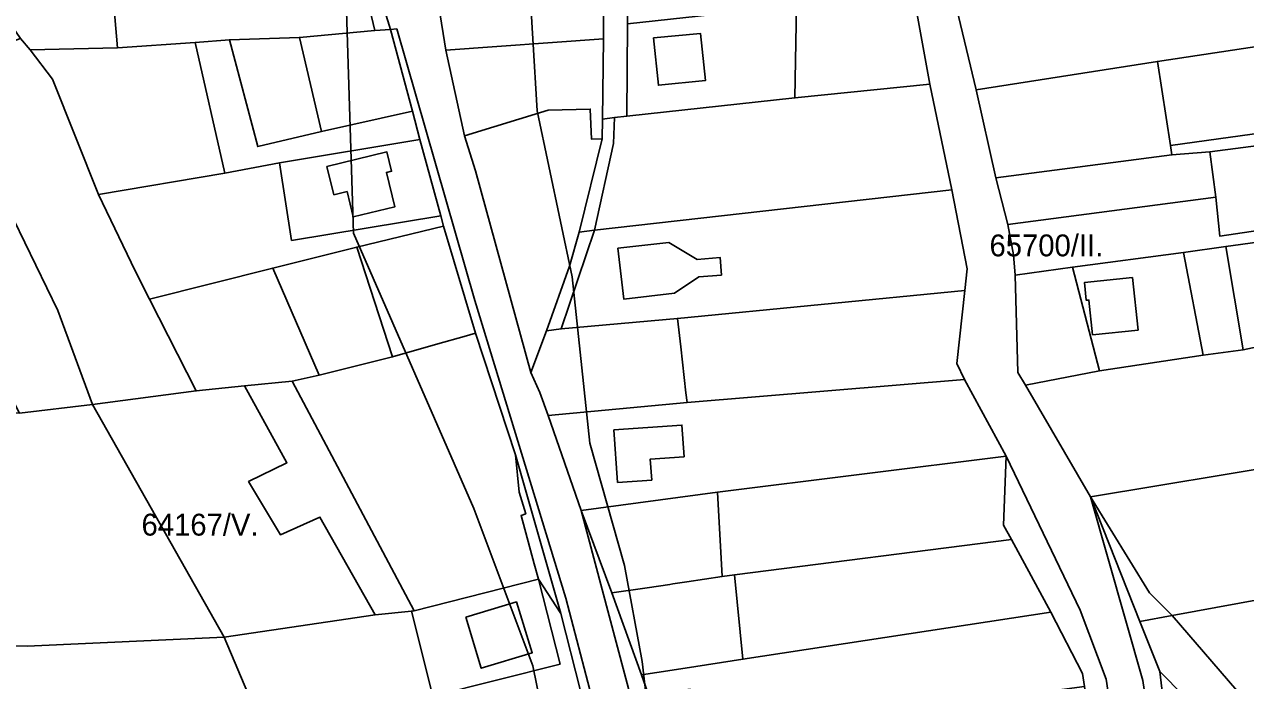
# Model space of a CAD drawing. Extents: x -521261 to -517465, y -1182764 to -1179456.
# Drawn here: x -519763.3 to -519484, y -1180677.3 to -1180527.3 of the extents above; entities that cross this region are included whole.
import ezdxf

# ---------------------------------------------------------------- set-up
doc = ezdxf.new("R2010")
doc.units = 0
for name, color, linetype in [('95560013', 7, 'Continuous'), ('95590013', 7, 'Continuous'), ('95600013', 7, 'Continuous'), ('95610013', 7, 'Continuous'), ('95630013', 7, 'Continuous'), ('95640013', 7, 'Continuous'), ('95660013', 7, 'Continuous')]:
    doc.layers.add(name, color=color, linetype=linetype)

msp = doc.modelspace()

# ---------------------------------------------------------------- linework, layer by layer
at = {"layer": '95560013'}
for points in [[(-519625.22, -1180519.95), (-519563.84, -1180512.91), (-519559.42, -1180523.34), (-519556.23, -1180540.88), (-519587.06, -1180544.07), (-519586.67, -1180522.95), (-519625.35, -1180527.12)], [(-519587.06, -1180544.07), (-519556.23, -1180540.88), (-519551.14, -1180565.07), (-519632.93, -1180574.33), (-519628.57, -1180554.5), (-519628.3, -1180548.57), (-519625.48, -1180548.2)]]:
    msp.add_lwpolyline(points, close=True, dxfattribs=at)
at = {"layer": '95590013'}
for points in [[(-519481.29, -1180509.48), (-519457.44, -1180505.68), (-519449, -1180527.32), (-519457.6, -1180528.65), (-519463.53, -1180529.56), (-519476.08, -1180531.51), (-519480.43, -1180532.18), (-519504.16, -1180535.7), (-519545.59, -1180542.18), (-519550.45, -1180521.83)], [(-519586.67, -1180522.95), (-519587.06, -1180544.07), (-519625.48, -1180548.2), (-519625.35, -1180527.12)], [(-519457.6, -1180528.65), (-519449, -1180527.32), (-519443.22, -1180543.16), (-519444.59, -1180547.12), (-519501.17, -1180554.98), (-519504.16, -1180535.7), (-519480.43, -1180532.18), (-519479.66, -1180537.12), (-519478.23, -1180546.41), (-519461.33, -1180543.8), (-519455.4, -1180542.88)], [(-519716.41, -1180530.74), (-519709.92, -1180555.2), (-519695.32, -1180551.74), (-519674.54, -1180547.09), (-519672.84, -1180553.61), (-519704.93, -1180558.88), (-519717.41, -1180561.26), (-519724.26, -1180531.4)], [(-519700.39, -1180530.21), (-519695.32, -1180551.74), (-519709.92, -1180555.2), (-519716.41, -1180530.74)], [(-519666.88, -1180533.11), (-519630.81, -1180530.53), (-519631.09, -1180548.95), (-519631.17, -1180553.45), (-519633.59, -1180553.49), (-519633.88, -1180546.6), (-519643.47, -1180546.88), (-519662.64, -1180552.73)], [(-519619.39, -1180530.32), (-519618.27, -1180541.18), (-519607.52, -1180540.08), (-519608.63, -1180529.33)], [(-519545.59, -1180542.18), (-519504.16, -1180535.7), (-519501.17, -1180554.98), (-519500.84, -1180557.1), (-519541.11, -1180562.36)], [(-519444.59, -1180547.12), (-519445.79, -1180550.4), (-519492.15, -1180556.42), (-519500.84, -1180557.1), (-519501.17, -1180554.98)], [(-519445.79, -1180550.4), (-519447.22, -1180555.01), (-519448.8, -1180555.21), (-519450.48, -1180568.08), (-519450.58, -1180569.86), (-519454.03, -1180570.32), (-519489.86, -1180575.7), (-519490.8, -1180566.75), (-519492.15, -1180556.42)], [(-519500.84, -1180557.1), (-519492.15, -1180556.42), (-519490.8, -1180566.75), (-519538.35, -1180572.99), (-519541.11, -1180562.36)], [(-519632.93, -1180574.33), (-519551.14, -1180565.07), (-519547.64, -1180583.16), (-519548.23, -1180588.14), (-519613.95, -1180594.5), (-519640.49, -1180596.89)], [(-519538.35, -1180572.99), (-519490.8, -1180566.75), (-519489.86, -1180575.7), (-519454.03, -1180570.32), (-519453.95, -1180573.29), (-519488.53, -1180578.08), (-519498.22, -1180579.41), (-519523.6, -1180582.79), (-519536.72, -1180584.57), (-519537.04, -1180579.93)], [(-519488.53, -1180578.08), (-519453.95, -1180573.29), (-519455.66, -1180597.28), (-519476.71, -1180600.04), (-519484.55, -1180601.67)], [(-519615.93, -1180577.1), (-519627.55, -1180578.46), (-519626.19, -1180590.08), (-519614.57, -1180588.72), (-519609.05, -1180585.01), (-519603.87, -1180584.59), (-519604.17, -1180580.55), (-519609.43, -1180580.99)], [(-519498.22, -1180579.41), (-519488.53, -1180578.08), (-519484.55, -1180601.67), (-519493.71, -1180602.87)], [(-519734.67, -1180590.12), (-519706.47, -1180582.97), (-519695.88, -1180607.5), (-519702.07, -1180608.86), (-519712.92, -1180609.9), (-519723.97, -1180611.09)], [(-519536.72, -1180584.57), (-519523.6, -1180582.79), (-519517.41, -1180606.51), (-519534.35, -1180609.75), (-519536.05, -1180606.88)], [(-519548.23, -1180588.14), (-519550.02, -1180604.84), (-519548.25, -1180608.47), (-519611.74, -1180613.76), (-519612.01, -1180611.52), (-519613.15, -1180600.98), (-519613.95, -1180594.5)], [(-519484.55, -1180601.67), (-519476.71, -1180600.04), (-519473.5, -1180627.72), (-519519.49, -1180635.3), (-519534.35, -1180609.75), (-519517.41, -1180606.51), (-519493.71, -1180602.87)], [(-519548.25, -1180608.47), (-519538.72, -1180626.02), (-519604.76, -1180634.22), (-519635.98, -1180638.42), (-519643.53, -1180616.69), (-519611.74, -1180613.76)], [(-519628.48, -1180619.97), (-519627.63, -1180632), (-519619.82, -1180631.47), (-519620.14, -1180626.68), (-519612.41, -1180626.15), (-519612.9, -1180618.91)], [(-519538.72, -1180626.02), (-519539.34, -1180641.78), (-519537.56, -1180645.04), (-519600.87, -1180653.15), (-519603.71, -1180653.57), (-519604.76, -1180634.22)], [(-519473.5, -1180627.72), (-519471.99, -1180627.46), (-519464.58, -1180655.8), (-519500.79, -1180662.46), (-519505.99, -1180657.26), (-519519.49, -1180635.3)], [(-519537.56, -1180645.04), (-519528.51, -1180661.68), (-519598.97, -1180672.46), (-519600.87, -1180653.15)], [(-519674.13, -1180661.38), (-519645.67, -1180654.18), (-519640.77, -1180673.57), (-519669.85, -1180680.93), (-519674.76, -1180661.45)], [(-519500.79, -1180662.46), (-519464.58, -1180655.8), (-519456.63, -1180686.88), (-519478.81, -1180687.89)], [(-519662.3, -1180662.86), (-519658.8, -1180674.51), (-519647.15, -1180670.98), (-519650.76, -1180659.34)], [(-519528.51, -1180661.68), (-519521.28, -1180675.74), (-519520.86, -1180678.68), (-519560.03, -1180683.88), (-519599.96, -1180689.65), (-519609.08, -1180691.16), (-519610.98, -1180679.31), (-519617.01, -1180680.21), (-519615.19, -1180692.17), (-519615.35, -1180692.21), (-519619.51, -1180692.9), (-519620.34, -1180681.18), (-519622.17, -1180676.01), (-519618.65, -1180675.5), (-519612.16, -1180674.5), (-519598.97, -1180672.46)], [(-519492.54, -1180686.48), (-519490.6, -1180689.84), (-519501.68, -1180691.54), (-519503.59, -1180675.27)]]:
    msp.add_lwpolyline(points, close=True, dxfattribs=at)
at = {"layer": '95600013'}
msp.add_lwpolyline([(-519708.21, -1180689.61), (-519717.59, -1180667.43), (-519683.07, -1180662.31), (-519674.76, -1180661.45), (-519669.85, -1180680.93), (-519640.77, -1180673.57), (-519645.67, -1180654.18), (-519640.61, -1180662.03), (-519636.11, -1180679.72)], dxfattribs=at)
at = {"layer": '95610013'}
for points in [[(-519701.4, -1180452.03), (-519683.11, -1180528.64), (-519700.39, -1180530.21), (-519716.41, -1180530.74), (-519724.26, -1180531.4), (-519741.98, -1180532.57), (-519742.58, -1180525.52), (-519747.26, -1180461.14), (-519737.48, -1180458.88), (-519711.33, -1180453.82)], [(-519755.56, -1180462.83), (-519747.26, -1180461.14), (-519742.58, -1180525.52), (-519741.98, -1180532.57), (-519762, -1180533.09), (-519764.17, -1180530.48), (-519769.07, -1180523.42), (-519771.26, -1180514.7)], [(-519670.07, -1180513.08), (-519630.86, -1180510.85), (-519630.85, -1180520.26), (-519630.81, -1180530.53), (-519666.88, -1180533.11)], [(-519762, -1180533.09), (-519756.87, -1180539.77), (-519746.34, -1180566.13), (-519737.99, -1180583.64), (-519734.67, -1180590.12), (-519723.97, -1180611.09), (-519747.7, -1180614.18), (-519755.66, -1180592.71), (-519768.22, -1180566.74), (-519787.11, -1180538.74), (-519764.17, -1180530.48)], [(-519724.26, -1180531.4), (-519717.41, -1180561.26), (-519746.34, -1180566.13), (-519756.87, -1180539.77), (-519762, -1180533.09), (-519741.98, -1180532.57)], [(-519787.11, -1180538.74), (-519768.22, -1180566.74), (-519755.66, -1180592.71), (-519747.7, -1180614.18), (-519764.44, -1180616.17), (-519787.86, -1180570.19), (-519797.31, -1180557.63), (-519806.32, -1180548.59), (-519809.29, -1180545.42), (-519790.04, -1180534.46)], [(-519717.41, -1180561.26), (-519704.93, -1180558.88), (-519702.19, -1180576.67), (-519668.07, -1180571.07), (-519667.42, -1180573.37), (-519687.29, -1180578.17), (-519706.47, -1180582.97), (-519734.67, -1180590.12), (-519737.99, -1180583.64), (-519746.34, -1180566.13)], [(-519723.97, -1180611.09), (-519712.92, -1180609.9), (-519703.26, -1180627.51), (-519712, -1180631.84), (-519704.72, -1180643.99), (-519695.69, -1180639.95), (-519683.07, -1180662.31), (-519717.59, -1180667.43), (-519747.7, -1180614.18)], [(-519764.44, -1180616.17), (-519747.7, -1180614.18), (-519717.59, -1180667.43), (-519762.68, -1180669.48), (-519814.85, -1180668.94), (-519850.9, -1180639.04), (-519846.5, -1180637.75), (-519801.28, -1180626.06), (-519801.81, -1180615.54)], [(-519717.59, -1180667.43), (-519708.21, -1180689.61), (-519692.2, -1180746.98), (-519697.59, -1180747.55), (-519712.21, -1180749.16), (-519717.76, -1180748.91), (-519756.77, -1180721.21), (-519783.25, -1180694.48), (-519803.71, -1180675.31), (-519814.85, -1180668.94), (-519762.68, -1180669.48)]]:
    msp.add_lwpolyline(points, close=True, dxfattribs=at)
at = {"layer": '95630013'}
for points in [[(-519550.45, -1180521.83), (-519545.59, -1180542.18), (-519541.11, -1180562.36), (-519538.35, -1180572.99), (-519537.04, -1180579.93), (-519536.72, -1180584.57), (-519536.05, -1180606.88), (-519534.35, -1180609.75), (-519519.49, -1180635.3), (-519507.5, -1180677.34), (-519496.47, -1180751.4), (-519475.99, -1180798.26), (-519473.15, -1180811.61), (-519470.44, -1180842.25), (-519488.4, -1180904.99), (-519493.48, -1180935.68), (-519491.42, -1180951.86), (-519435.57, -1181123.54)], [(-519435.91, -1181162.44), (-519445.77, -1181119.72), (-519502.58, -1180941.01), (-519495.82, -1180898.23), (-519478.12, -1180840), (-519478.91, -1180815.91), (-519482.79, -1180802.48), (-519493.4, -1180779.68), (-519502.51, -1180755.33), (-519501.84, -1180755.2), (-519503.49, -1180741.14), (-519501.57, -1180737.28), (-519506.63, -1180738.29), (-519515.84, -1180677.04), (-519521.8, -1180661.26), (-519538.72, -1180626.02), (-519548.25, -1180608.47), (-519550.02, -1180604.84), (-519548.23, -1180588.14), (-519547.64, -1180583.16), (-519551.14, -1180565.07), (-519556.23, -1180540.88), (-519559.42, -1180523.34)]]:
    msp.add_lwpolyline(points, dxfattribs=at)
at = {"layer": '95640013'}
for points in [[(-519694.63, -1180450.22), (-519691.65, -1180449.59), (-519692.37, -1180457.96), (-519690.13, -1180486.31), (-519687.23, -1180503.42), (-519679.53, -1180528.4), (-519683.11, -1180528.64), (-519701.4, -1180452.03)], [(-519628.28, -1180520.14), (-519625.22, -1180519.95), (-519625.35, -1180527.12), (-519625.48, -1180548.2), (-519628.3, -1180548.57), (-519631.09, -1180548.95), (-519630.81, -1180530.53), (-519630.85, -1180520.26)], [(-519679.53, -1180528.4), (-519674.54, -1180547.09), (-519695.32, -1180551.74), (-519700.39, -1180530.21), (-519683.11, -1180528.64)], [(-519679.53, -1180528.4), (-519678.14, -1180528.26), (-519660.28, -1180590.39), (-519639.42, -1180658.51), (-519627.69, -1180703.31), (-519621.7, -1180754.65), (-519612.88, -1180837.19), (-519614.08, -1180840.87), (-519614.64, -1180835.3), (-519615.35, -1180828.28), (-519617.19, -1180812.47), (-519623.23, -1180754.54), (-519625.42, -1180734.42), (-519626.72, -1180725.27), (-519629.82, -1180703.66), (-519634.45, -1180685.74), (-519636.11, -1180679.72), (-519640.61, -1180662.03), (-519650.98, -1180625.68), (-519660.08, -1180597.91), (-519667.42, -1180573.37), (-519668.07, -1180571.07), (-519672.84, -1180553.61), (-519674.54, -1180547.09)], [(-519619.39, -1180530.32), (-519608.63, -1180529.33), (-519607.52, -1180540.08), (-519618.27, -1180541.18)], [(-519643.47, -1180546.88), (-519633.88, -1180546.6), (-519633.59, -1180553.49), (-519631.17, -1180553.45), (-519636.38, -1180574.78), (-519638.58, -1180582.52), (-519643.86, -1180597.34), (-519647.49, -1180606.85), (-519660.09, -1180560.72), (-519662.64, -1180552.73)], [(-519628.3, -1180548.57), (-519628.57, -1180554.5), (-519632.93, -1180574.33), (-519636.38, -1180574.78), (-519631.17, -1180553.45), (-519631.09, -1180548.95)], [(-519704.93, -1180558.88), (-519672.84, -1180553.61), (-519668.07, -1180571.07), (-519702.19, -1180576.67)], [(-519694.09, -1180559.75), (-519692.51, -1180566.21), (-519689.5, -1180565.48), (-519688.09, -1180571.28), (-519678.56, -1180568.97), (-519680.48, -1180561.11), (-519679.31, -1180560.83), (-519680.38, -1180556.41)], [(-519694.09, -1180559.75), (-519680.38, -1180556.41), (-519679.31, -1180560.83), (-519680.48, -1180561.11), (-519678.56, -1180568.97), (-519688.09, -1180571.28), (-519689.5, -1180565.48), (-519692.51, -1180566.21)], [(-519667.42, -1180573.37), (-519660.08, -1180597.91), (-519662.73, -1180598.66), (-519668.74, -1180600.35), (-519679.07, -1180603.27), (-519687.29, -1180578.17)], [(-519632.93, -1180574.33), (-519640.49, -1180596.89), (-519643.86, -1180597.34), (-519638.58, -1180582.52), (-519636.38, -1180574.78)], [(-519687.29, -1180578.17), (-519679.07, -1180603.27), (-519695.88, -1180607.5), (-519706.47, -1180582.97)], [(-519615.93, -1180577.1), (-519609.43, -1180580.99), (-519604.17, -1180580.55), (-519603.87, -1180584.59), (-519609.05, -1180585.01), (-519614.57, -1180588.72), (-519626.19, -1180590.08), (-519627.55, -1180578.46)], [(-519523.6, -1180582.79), (-519498.22, -1180579.41), (-519493.71, -1180602.87), (-519517.41, -1180606.51)], [(-519509.82, -1180585.16), (-519508.57, -1180597.16), (-519518.96, -1180598.25), (-519519.82, -1180590.3), (-519520.41, -1180590.36), (-519520.84, -1180586.31)], [(-519509.82, -1180585.16), (-519520.84, -1180586.31), (-519520.41, -1180590.36), (-519519.82, -1180590.3), (-519518.96, -1180598.25), (-519508.57, -1180597.16)], [(-519640.49, -1180596.89), (-519613.95, -1180594.5), (-519613.15, -1180600.98), (-519612.01, -1180611.52), (-519611.74, -1180613.76), (-519643.53, -1180616.69), (-519645.43, -1180611.45), (-519647.49, -1180606.85), (-519643.86, -1180597.34)], [(-519662.73, -1180598.66), (-519660.08, -1180597.91), (-519650.98, -1180625.68), (-519650.1, -1180634.22), (-519648.62, -1180639.19), (-519649.68, -1180639.62), (-519646.72, -1180650.66), (-519645.67, -1180654.18), (-519674.13, -1180661.38), (-519702.07, -1180608.86), (-519695.88, -1180607.5), (-519679.07, -1180603.27), (-519668.74, -1180600.35)], [(-519712.92, -1180609.9), (-519702.07, -1180608.86), (-519674.13, -1180661.38), (-519674.76, -1180661.45), (-519683.07, -1180662.31), (-519695.69, -1180639.95), (-519704.72, -1180643.99), (-519712, -1180631.84), (-519703.26, -1180627.51)], [(-519628.48, -1180619.97), (-519612.9, -1180618.91), (-519612.41, -1180626.15), (-519620.14, -1180626.68), (-519619.82, -1180631.47), (-519627.63, -1180632)], [(-519650.98, -1180625.68), (-519640.61, -1180662.03), (-519645.67, -1180654.18), (-519646.72, -1180650.66), (-519649.68, -1180639.62), (-519648.62, -1180639.19), (-519650.1, -1180634.22)], [(-519539.34, -1180641.78), (-519538.72, -1180626.02), (-519521.8, -1180661.26), (-519515.84, -1180677.04), (-519506.63, -1180738.29), (-519511.64, -1180739.35), (-519514.02, -1180722.61), (-519516.57, -1180706.21), (-519518.61, -1180693.85), (-519520.86, -1180678.68), (-519521.28, -1180675.74), (-519528.51, -1180661.68), (-519537.56, -1180645.04)], [(-519635.98, -1180638.42), (-519604.76, -1180634.22), (-519603.71, -1180653.57), (-519611.75, -1180654.75), (-519614.96, -1180655.24), (-519615.7, -1180655.35), (-519620.83, -1180656.1), (-519621.42, -1180656.2), (-519628.93, -1180657.31)], [(-519519.49, -1180635.3), (-519505.99, -1180657.26), (-519500.79, -1180662.46), (-519508.15, -1180663.81)], [(-519635.98, -1180638.42), (-519628.93, -1180657.31), (-519622.17, -1180676.01), (-519620.34, -1180681.18), (-519619.51, -1180692.9), (-519618.34, -1180708.21), (-519621.2, -1180693.8)], [(-519600.87, -1180653.15), (-519598.97, -1180672.46), (-519612.16, -1180674.5), (-519618.65, -1180675.5), (-519622.17, -1180676.01), (-519628.93, -1180657.31), (-519621.42, -1180656.2), (-519620.83, -1180656.1), (-519615.7, -1180655.35), (-519614.96, -1180655.24), (-519611.75, -1180654.75), (-519603.71, -1180653.57)], [(-519662.3, -1180662.86), (-519650.76, -1180659.34), (-519647.15, -1180670.98), (-519658.8, -1180674.51)], [(-519508.15, -1180663.81), (-519500.79, -1180662.46), (-519478.81, -1180687.89), (-519490.6, -1180689.84), (-519492.54, -1180686.48), (-519503.59, -1180675.27)]]:
    msp.add_lwpolyline(points, close=True, dxfattribs=at)
for points in [[(-519627.69, -1180703.31), (-519639.42, -1180658.51), (-519660.28, -1180590.39), (-519678.14, -1180528.26), (-519679.53, -1180528.4), (-519687.23, -1180503.42)], [(-519670.07, -1180513.08), (-519666.88, -1180533.11), (-519662.64, -1180552.73), (-519660.09, -1180560.72), (-519647.49, -1180606.85), (-519645.43, -1180611.45), (-519643.53, -1180616.69), (-519635.98, -1180638.42), (-519621.2, -1180693.8)], [(-519475.99, -1180798.26), (-519496.47, -1180751.4), (-519507.5, -1180677.34), (-519519.49, -1180635.3), (-519508.15, -1180663.81), (-519503.59, -1180675.27), (-519501.68, -1180691.54), (-519499.82, -1180703.19), (-519496.79, -1180719.89), (-519495.56, -1180726.51), (-519494.71, -1180730.9), (-519492.42, -1180742.78), (-519492.22, -1180746.44), (-519490.66, -1180750.76), (-519482.84, -1180772.64)]]:
    msp.add_lwpolyline(points, dxfattribs=at)
at = {"layer": '95660013'}
for points in [[(-519778.5, -1180863.5), (-519754.5, -1180885.5), (-519732, -1180892.5), (-519706, -1180886.5), (-519690, -1180877), (-519657.5, -1180851.5), (-519641, -1180832), (-519634.5, -1180816), (-519628.5, -1180786.5), (-519629, -1180748), (-519641.5, -1180701), (-519647, -1180674), (-519660.5, -1180638), (-519688, -1180575), (-519690, -1180512), (-519694, -1180449), (-519702.5, -1180422), (-519713, -1180407), (-519724.5, -1180398.5), (-519739, -1180397), (-519775, -1180405)], [(-519775, -1180405), (-519739, -1180397), (-519724.5, -1180398.5), (-519713, -1180407), (-519702.5, -1180422), (-519694, -1180449), (-519690, -1180512), (-519688, -1180575), (-519660.5, -1180638), (-519647, -1180674), (-519641.5, -1180701), (-519629, -1180748), (-519628.5, -1180786.5), (-519634.5, -1180816), (-519641, -1180832), (-519657.5, -1180851.5), (-519690, -1180877), (-519706, -1180886.5), (-519732, -1180892.5), (-519754.5, -1180885.5), (-519778.5, -1180863.5)], [(-519648, -1180514), (-519646, -1180547), (-519638, -1180585), (-519634, -1180623), (-519626, -1180651), (-519622, -1180673), (-519616, -1180725), (-519612, -1180765), (-519608, -1180807), (-519606, -1180845), (-519610, -1180864), (-519635, -1180880), (-519671, -1180896.5), (-519721, -1180917.5), (-519739.5, -1180929), (-519767.5, -1180952)], [(-519630, -1180937), (-519624, -1180919), (-519618, -1180898), (-519612, -1180879), (-519610, -1180864), (-519606, -1180845), (-519608, -1180807), (-519612, -1180765), (-519616, -1180725), (-519622, -1180673), (-519626, -1180651), (-519634, -1180623), (-519638, -1180585), (-519646, -1180547), (-519648, -1180514)]]:
    msp.add_lwpolyline(points, dxfattribs=at)

# ---------------------------------------------------------------- texts
for s, p in [('65700/II.', (-519542.55, -1180580.3)), ('64167/V.', (-519736.5, -1180644.18))]:
    msp.add_text(s, height=5, rotation=360, dxfattribs=at).set_placement(p)

doc.saveas('drawing.dxf')
